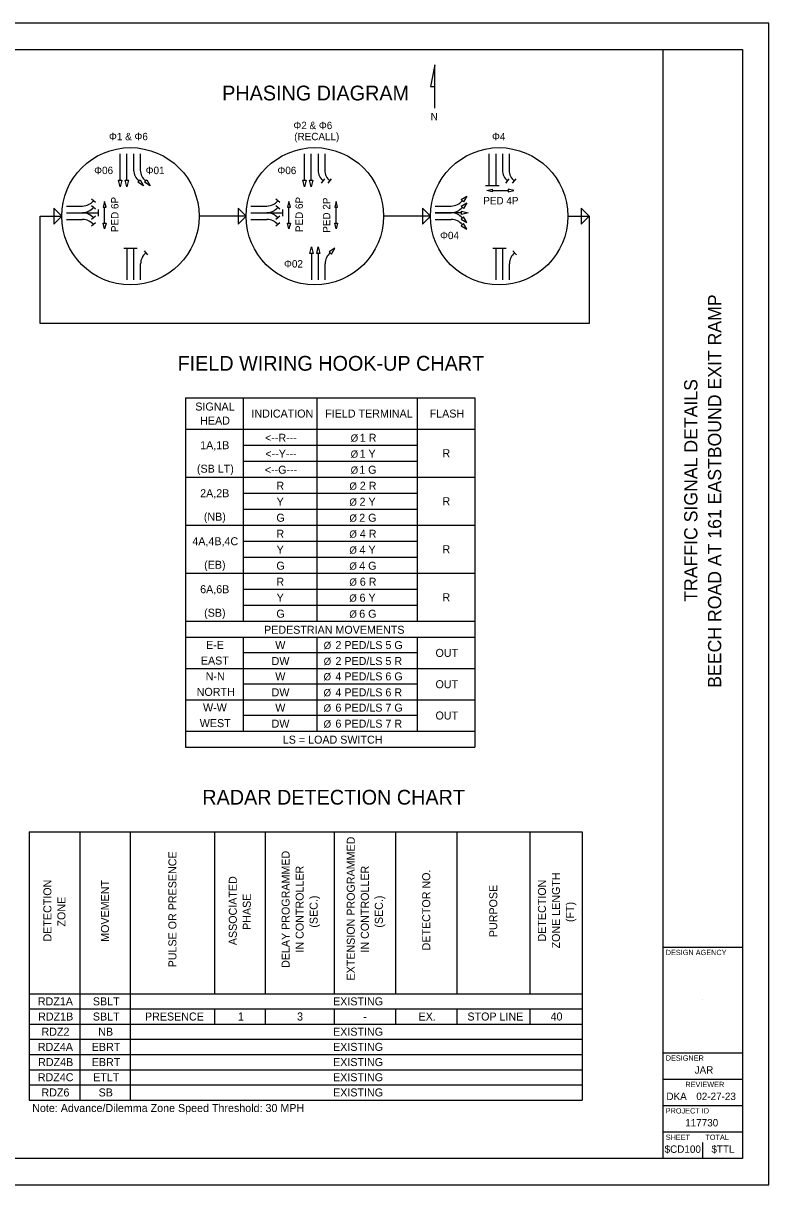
# Model space of a CAD drawing. Extents: x 0 to 34, y 0 to 22.
# Drawn here: x 19.89 to 34, y 0 to 22 of the extents above; entities that cross this region are included whole.
import ezdxf

# ---------------------------------------------------------------- set-up
doc = ezdxf.new("R2010")
doc.units = 0
for name, color, linetype in [('SG_P_Text', 7, 'Continuous'), ('SH_Border', 7, 'Continuous'), ('SH_Cut_Line', 7, 'Continuous'), ('SH_Data', 7, 'Continuous'), ('SH_Text', 7, 'Continuous')]:
    doc.layers.add(name, color=color, linetype=linetype)

msp = doc.modelspace()

# ---------------------------------------------------------------- linework, layer by layer
at = {"layer": 'SG_P_Text'}
for p, q in [((21.726, 19.026), (21.726, 19.524)), ((21.853, 19.026), (21.853, 19.524)), ((21.98, 19.524), (21.98, 19.218)), ((22.106, 19.524), (22.106, 19.218)), ((25.216, 19.026), (25.216, 19.524)), ((25.342, 19.026), (25.342, 19.524)), ((25.469, 19.524), (25.469, 19.218)), ((25.596, 19.524), (25.596, 19.218)), ((28.705, 19.524), (28.705, 18.923)), ((28.832, 19.524), (28.832, 18.923)), ((28.959, 19.524), (28.959, 19.218)), ((29.086, 19.524), (29.086, 19.218)), ((25.536, 18.972), (25.6, 19.051)), ((25.663, 18.972), (25.727, 19.051)), ((28.769, 18.923), (28.642, 18.923)), ((28.896, 18.923), (28.769, 18.923)), ((29.026, 18.972), (29.09, 19.051)), ((29.153, 18.972), (29.217, 19.051)), ((28.766, 18.832), (29.071, 18.832)), ((20.707, 18.538), (21.013, 18.538)), ((21.259, 18.605), (21.18, 18.669)), ((21.259, 18.478), (21.18, 18.543)), ((21.431, 18.213), (21.431, 18.518)), ((24.197, 18.538), (24.503, 18.538)), ((24.749, 18.605), (24.669, 18.669)), ((24.749, 18.478), (24.669, 18.543)), ((24.92, 18.213), (24.92, 18.518)), ((25.815, 18.213), (25.815, 18.518)), ((27.687, 18.538), (27.992, 18.538)), ((20.707, 18.412), (21.308, 18.412)), ((20.707, 18.412), (21.013, 18.412)), ((20.707, 18.412), (21.013, 18.412)), ((20.707, 18.285), (21.013, 18.285)), ((21.259, 18.345), (21.18, 18.281)), ((21.308, 18.475), (21.308, 18.348)), ((24.108, 18.344), (23.218, 18.344)), ((24.197, 18.412), (24.798, 18.412)), ((24.197, 18.412), (24.503, 18.412)), ((24.197, 18.412), (24.503, 18.412)), ((24.197, 18.285), (24.503, 18.285)), ((24.749, 18.345), (24.669, 18.281)), ((24.798, 18.475), (24.798, 18.348)), ((27.598, 18.344), (26.707, 18.344)), ((27.687, 18.412), (27.992, 18.412)), ((28.185, 18.412), (27.687, 18.412)), ((27.687, 18.412), (27.992, 18.412)), ((27.687, 18.285), (27.992, 18.285)), ((21.259, 18.218), (21.18, 18.154)), ((24.749, 18.218), (24.669, 18.154)), ((21.795, 17.74), (21.922, 17.74)), ((21.859, 17.139), (21.859, 17.74)), ((21.922, 17.74), (22.049, 17.74)), ((21.985, 17.139), (21.985, 17.74)), ((22.179, 17.691), (22.243, 17.611)), ((25.348, 17.637), (25.348, 17.139)), ((25.475, 17.637), (25.475, 17.139)), ((28.775, 17.74), (28.901, 17.74)), ((28.838, 17.139), (28.838, 17.74)), ((28.901, 17.74), (29.028, 17.74)), ((28.965, 17.139), (28.965, 17.74)), ((29.159, 17.691), (29.223, 17.611)), ((22.112, 17.139), (22.112, 17.445)), ((25.602, 17.139), (25.602, 17.445)), ((29.092, 17.139), (29.092, 17.445))]:
    msp.add_line(p, q, dxfattribs=at)
for points in [[(21.757, 19.026), (21.726, 18.901), (21.695, 19.026)], [(21.884, 19.026), (21.853, 18.901), (21.821, 19.026)], [(22.101, 19.034), (22.167, 18.923), (22.056, 18.989)], [(22.227, 19.034), (22.294, 18.923), (22.183, 18.989)], [(25.247, 19.026), (25.216, 18.901), (25.184, 19.026)], [(25.374, 19.026), (25.342, 18.901), (25.311, 19.026)], [(28.177, 18.659), (28.287, 18.726), (28.221, 18.615)], [(28.766, 18.806), (28.662, 18.832), (28.766, 18.858)], [(29.071, 18.806), (29.175, 18.832), (29.071, 18.858)], [(20.618, 18.344), (20.467, 18.496), (20.467, 18.193)], [(21.457, 18.518), (21.431, 18.622), (21.405, 18.518)], [(24.108, 18.344), (23.957, 18.496), (23.956, 18.193)], [(24.946, 18.518), (24.92, 18.622), (24.894, 18.518)], [(25.841, 18.518), (25.815, 18.622), (25.789, 18.518)], [(27.598, 18.344), (27.446, 18.496), (27.446, 18.193)], [(28.177, 18.533), (28.287, 18.599), (28.221, 18.488)], [(30.603, 18.344), (30.452, 18.496), (30.452, 18.193)], [(28.177, 18.29), (28.287, 18.224), (28.221, 18.335)], [(28.185, 18.443), (28.31, 18.412), (28.185, 18.38)], [(21.457, 18.213), (21.431, 18.108), (21.405, 18.213)], [(24.946, 18.213), (24.92, 18.108), (24.894, 18.213)], [(25.841, 18.213), (25.815, 18.108), (25.789, 18.213)], [(28.177, 18.164), (28.287, 18.098), (28.221, 18.208)], [(25.317, 17.637), (25.348, 17.762), (25.38, 17.637)], [(25.444, 17.637), (25.475, 17.762), (25.506, 17.637)], [(25.723, 17.629), (25.789, 17.74), (25.679, 17.673)]]:
    msp.add_lwpolyline(points, close=True, dxfattribs=at)
msp.add_lwpolyline([(30.197, 18.344), (30.603, 18.344), (30.603, 16.314), (20.618, 16.313), (20.212, 16.313), (20.212, 18.344), (20.618, 18.344)], dxfattribs=at)
for centre in [(21.918, 18.344), (25.408, 18.344), (28.897, 18.344)]:
    msp.add_circle(centre, 1.3, dxfattribs=at)
for centre, start, end in [((22.245, 19.218), 180, 231.2007), ((22.371, 19.218), 180, 231.2007), ((25.734, 19.218), 180, 231.2007), ((25.861, 19.218), 180, 231.2007), ((29.224, 19.218), 180, 231.2007), ((29.351, 19.218), 180, 231.2007), ((21.013, 18.803), 270, 321.2007), ((21.013, 18.677), 270, 321.2007), ((24.503, 18.803), 270, 321.2007), ((24.503, 18.677), 270, 321.2007), ((27.992, 18.803), 270, 321.2007), ((27.992, 18.677), 270, 321.2007), ((21.013, 18.147), 38.7993, 90), ((21.013, 18.02), 38.7993, 90), ((24.503, 18.147), 38.7993, 90), ((24.503, 18.02), 38.7993, 90), ((27.992, 18.147), 38.7993, 90), ((27.992, 18.02), 38.7993, 90), ((22.377, 17.445), 128.7993, 180), ((25.867, 17.445), 128.8122, 180.0129), ((29.357, 17.445), 128.7993, 180)]:
    msp.add_arc(centre, 0.265, start, end, dxfattribs=at)
at = {"layer": 'SH_Border'}
for p, q in [((32, 0.5), (32, 21.5)), ((32, 4.5), (33.5, 4.5)), ((32, 2.5), (33.5, 2.5)), ((32, 2), (33.5, 2)), ((32, 1.5), (33.5, 1.5)), ((32, 1), (33.5, 1))]:
    msp.add_line(p, q, dxfattribs=at)
msp.add_lwpolyline([(1.5, 21.5), (33.5, 21.5), (33.5, 0.5), (1.5, 0.5)], close=True, dxfattribs=at)
at = {"layer": 'SH_Cut_Line'}
msp.add_lwpolyline([(0, 0), (34, 0), (34, 22), (0, 22)], close=True, dxfattribs=at)
at = {"layer": 'SH_Data'}
for p, q in [((32.75, 3.5), (32.75, 3.5)), ((32.375, 0.675), (32.375, 0.675)), ((32.75, 0.5), (32.75, 0.8))]:
    msp.add_line(p, q, dxfattribs=at)
at = {"layer": 'SH_Text'}
for p, q in [((27.677, 20.389), (27.677, 21.209)), ((22.958, 14.903), (28.439, 14.903)), ((22.958, 14.903), (22.958, 14.007)), ((24.051, 14.903), (24.051, 14.007)), ((25.448, 14.903), (25.448, 14.007)), ((27.345, 14.903), (27.345, 14.007)), ((28.439, 14.903), (28.439, 14.007)), ((22.958, 14.31), (28.439, 14.31)), ((22.958, 14.007), (22.958, 13.401)), ((24.051, 14.007), (27.345, 14.007)), ((24.051, 14.007), (24.051, 13.401)), ((25.448, 14.007), (25.448, 13.401)), ((27.345, 14.007), (27.345, 13.401)), ((28.439, 14.007), (28.439, 13.401)), ((24.051, 13.704), (27.345, 13.704)), ((22.958, 13.401), (28.439, 13.401)), ((22.958, 13.401), (22.958, 11.886)), ((24.051, 13.401), (24.051, 11.886)), ((25.448, 13.401), (25.448, 11.886)), ((27.345, 13.401), (27.345, 11.886)), ((28.439, 13.401), (28.439, 11.886)), ((24.051, 13.098), (27.345, 13.098)), ((24.051, 12.795), (27.345, 12.795)), ((22.958, 12.492), (28.439, 12.492)), ((24.051, 12.189), (27.345, 12.189)), ((22.958, 11.886), (22.958, 11.583)), ((24.051, 11.886), (27.345, 11.886)), ((24.051, 11.886), (24.051, 11.583)), ((25.448, 11.886), (25.448, 11.583)), ((27.345, 11.886), (27.345, 11.583)), ((28.439, 11.886), (28.439, 11.583)), ((22.958, 11.583), (28.439, 11.583)), ((22.958, 11.583), (22.958, 11.28)), ((24.051, 11.583), (24.051, 11.28)), ((25.448, 11.583), (25.448, 11.28)), ((27.345, 11.583), (27.345, 11.28)), ((28.439, 11.583), (28.439, 11.28)), ((22.958, 11.28), (22.958, 10.674)), ((24.051, 11.28), (27.345, 11.28)), ((24.051, 11.28), (24.051, 10.674)), ((25.448, 11.28), (25.448, 10.674)), ((27.345, 11.28), (27.345, 10.674)), ((28.439, 11.28), (28.439, 10.674)), ((24.051, 10.977), (27.345, 10.977)), ((22.958, 10.674), (28.439, 10.674)), ((22.958, 10.674), (22.958, 9.488)), ((28.439, 10.674), (28.439, 9.488)), ((22.958, 10.371), (28.439, 10.371)), ((24.051, 10.371), (24.051, 9.488)), ((25.448, 10.371), (25.448, 9.488)), ((27.345, 10.371), (27.345, 9.488)), ((24.051, 10.081), (27.345, 10.081)), ((22.958, 9.778), (28.439, 9.778)), ((22.958, 9.488), (22.958, 9.185)), ((24.051, 9.488), (27.345, 9.488)), ((24.051, 9.488), (24.051, 9.185)), ((25.448, 9.488), (25.448, 9.185)), ((27.345, 9.488), (27.345, 9.185)), ((28.439, 9.488), (28.439, 9.185)), ((22.958, 9.185), (28.439, 9.185)), ((22.958, 9.185), (22.958, 8.895)), ((24.051, 9.185), (24.051, 8.895)), ((25.448, 9.185), (25.448, 8.895)), ((27.345, 9.185), (27.345, 8.895)), ((28.439, 9.185), (28.439, 8.895)), ((22.958, 8.895), (22.958, 8.592)), ((24.051, 8.895), (27.345, 8.895)), ((24.051, 8.895), (24.051, 8.592)), ((25.448, 8.895), (25.448, 8.592)), ((27.345, 8.895), (27.345, 8.592)), ((28.439, 8.895), (28.439, 8.592)), ((22.958, 8.592), (28.439, 8.592)), ((22.958, 8.592), (22.958, 8.289)), ((28.439, 8.592), (28.439, 8.289)), ((22.958, 8.289), (28.439, 8.289)), ((20, 6.684), (25.774, 6.684)), ((20, 6.684), (20, 2.755)), ((20.959, 6.684), (20.959, 2.755)), ((21.917, 6.684), (21.917, 2.755)), ((23.51, 6.684), (23.51, 3.618)), ((24.468, 6.684), (24.468, 3.618)), ((25.774, 6.684), (28.098, 6.684)), ((25.774, 6.684), (25.774, 3.618)), ((26.936, 6.684), (26.936, 3.618)), ((28.098, 6.684), (30.47, 6.684)), ((28.098, 6.684), (28.098, 3.618)), ((29.475, 6.684), (29.475, 3.618)), ((30.47, 6.684), (30.47, 2.755)), ((20, 3.618), (25.774, 3.618)), ((25.774, 3.618), (28.098, 3.618)), ((28.098, 3.618), (30.47, 3.618)), ((20, 3.33), (25.774, 3.33)), ((23.51, 3.33), (23.51, 3.043)), ((24.468, 3.33), (24.468, 3.043)), ((25.774, 3.33), (28.098, 3.33)), ((25.774, 3.33), (25.774, 3.043)), ((26.936, 3.33), (26.936, 3.043)), ((28.098, 3.33), (30.47, 3.33)), ((28.098, 3.33), (28.098, 3.043)), ((29.475, 3.33), (29.475, 3.043)), ((20, 3.043), (25.774, 3.043)), ((25.774, 3.043), (28.098, 3.043)), ((28.098, 3.043), (30.47, 3.043)), ((20, 2.755), (25.774, 2.755)), ((20, 2.755), (20, 1.893)), ((20.959, 2.755), (20.959, 1.893)), ((21.917, 2.755), (21.917, 1.893)), ((25.774, 2.755), (28.098, 2.755)), ((28.098, 2.755), (30.47, 2.755)), ((30.47, 2.755), (30.47, 1.893)), ((20, 2.468), (25.774, 2.468)), ((25.774, 2.468), (28.098, 2.468)), ((28.098, 2.468), (30.47, 2.468)), ((20, 2.18), (25.774, 2.18)), ((25.774, 2.18), (28.098, 2.18)), ((28.098, 2.18), (30.47, 2.18)), ((20, 1.893), (25.774, 1.893)), ((20, 1.893), (20, 1.605)), ((20.959, 1.893), (20.959, 1.605)), ((21.917, 1.893), (21.917, 1.605)), ((25.774, 1.893), (28.098, 1.893)), ((28.098, 1.893), (30.47, 1.893)), ((30.47, 1.893), (30.47, 1.605)), ((20, 1.605), (25.774, 1.605)), ((25.774, 1.605), (28.098, 1.605)), ((28.098, 1.605), (30.47, 1.605))]:
    msp.add_line(p, q, dxfattribs=at)
msp.add_lwpolyline([(27.677, 21.209), (27.595, 20.799), (27.677, 20.799)], close=True, dxfattribs=at)

# ---------------------------------------------------------------- texts
at = {"layer": 'SG_P_Text'}
for s, height, p in [('PHASING DIAGRAM', 0.28, (23.655, 20.538)), ('Φ2 & Φ6', 0.14, (25.003, 19.994)), ('Φ1 & Φ6', 0.14, (21.513, 19.784)), ('(RECALL)', 0.14, (25.019, 19.784)), ('Φ4', 0.14, (28.762, 19.784)), ('Φ06', 0.14, (21.233, 19.142)), ('Φ01', 0.14, (22.207, 19.142)), ('Φ06', 0.14, (24.701, 19.142)), ('PED 4P', 0.14, (28.597, 18.569)), ('Φ04', 0.14, (27.779, 17.91)), ('Φ02', 0.14, (24.826, 17.373)), ('FIELD WIRING HOOK-UP CHART', 0.28, (22.811, 15.419)), ('RADAR DETECTION CHART', 0.28, (23.279, 7.2))]:
    msp.add_text(s, height=height, dxfattribs=at).set_placement(p)
for s, p in [('PED 6P', (21.693, 18.044)), ('PED 6P', (25.183, 18.044)), ('PED 2P', (25.701, 18.032))]:
    msp.add_text(s, height=0.14, rotation=90, dxfattribs=at).set_placement(p)
at = {"layer": 'SH_Data'}
for s, p in [('BEECH ROAD AT 161 EASTBOUND EXIT RAMP', (33.1, 9.414)), ('TRAFFIC SIGNAL DETAILS', (32.65, 11.043))]:
    msp.add_text(s, height=0.25, rotation=90, dxfattribs=at).set_placement(p)
for s, height, p in [('DESIGN AGENCY', 0.1, (32.05, 4.35)), ('DESIGNER', 0.1, (32.05, 2.35)), ('JAR', 0.14, (32.597, 2.105)), ('REVIEWER', 0.1, (32.422, 1.85)), ('DKA', 0.14, (32.063, 1.605)), ('02-27-23', 0.14, (32.629, 1.605)), ('PROJECT ID', 0.1, (32.05, 1.35)), ('117730', 0.14, (32.419, 1.105)), ('SHEET', 0.1, (32.05, 0.85)), ('TOTAL', 0.1, (32.8, 0.85)), ('$CD100', 0.14, (32.029, 0.605)), ('$TTL', 0.14, (32.915, 0.605))]:
    msp.add_text(s, height=height, dxfattribs=at).set_placement(p)
at = {"layer": 'SH_Text'}
for s, height, p in [('N', 0.14, (27.601, 20.161)), ('SIGNAL ', 0.1515, (23.147, 14.664)), ('HEAD', 0.1515, (23.239, 14.398)), ('INDICATION', 0.1515, (24.209, 14.531)), ('FIELD TERMINAL', 0.15153, (25.606, 14.531)), ('FLASH', 0.1515, (27.582, 14.531)), ('1A,1B', 0.1515, (23.239, 13.932)), ('<--R---', 0.1515, (24.467, 14.073)), ('Ø', 0.137, (26.087, 14.075)), ('1 R', 0.1515, (26.26, 14.073)), ('<--Y---', 0.1515, (24.473, 13.77)), ('Ø', 0.137, (26.087, 13.771)), ('1 Y', 0.1515, (26.255, 13.77)), ('R', 0.152, (27.824, 13.78)), ('(SB LT)', 0.1515, (23.178, 13.487)), ('<--G---', 0.1515, (24.462, 13.467)), ('Ø', 0.137, (26.087, 13.468)), ('1 G', 0.1515, (26.249, 13.467)), ('R', 0.152, (24.681, 13.164)), ('Ø', 0.137, (26.064, 13.165)), ('2 R', 0.1515, (26.26, 13.164)), ('2A,2B', 0.1515, (23.239, 13.022)), ('Y', 0.152, (24.686, 12.861)), ('Ø', 0.137, (26.063, 12.862)), ('2 Y', 0.1515, (26.255, 12.861)), ('R', 0.152, (27.824, 12.871)), ('(NB)', 0.1515, (23.308, 12.578)), ('G', 0.152, (24.681, 12.558)), ('Ø', 0.137, (26.064, 12.559)), ('2 G', 0.1515, (26.249, 12.558)), ('R', 0.152, (24.681, 12.255)), ('Ø', 0.137, (26.062, 12.256)), ('4 R', 0.1515, (26.26, 12.255)), ('4A,4B,4C', 0.1515, (23.091, 12.113)), ('Y', 0.152, (24.686, 11.952)), ('4 Y', 0.1515, (26.255, 11.952)), ('R', 0.152, (27.824, 11.962)), ('Ø', 0.137, (26.062, 11.953)), ('(EB)', 0.1515, (23.314, 11.668)), ('G', 0.152, (24.681, 11.649)), ('Ø', 0.137, (26.062, 11.65)), ('4 G', 0.1515, (26.249, 11.649)), ('R', 0.152, (24.681, 11.346)), ('Ø', 0.137, (26.062, 11.347)), ('6 R', 0.1515, (26.26, 11.346)), ('6A,6B', 0.1515, (23.239, 11.204)), ('Y', 0.152, (24.686, 11.043)), ('Ø', 0.137, (26.061, 11.044)), ('6 Y', 0.1515, (26.255, 11.043)), ('R', 0.152, (27.824, 11.052)), ('(SB)', 0.1515, (23.314, 10.759)), ('G', 0.152, (24.681, 10.74)), ('Ø', 0.137, (26.062, 10.741)), ('6 G', 0.1515, (26.249, 10.74)), ('PEDESTRIAN MOVEMENTS', 0.15153, (24.448, 10.436)), ('E-E', 0.1515, (23.35, 10.15)), ('W', 0.152, (24.66, 10.147)), ('Ø', 0.137, (25.576, 10.148)), ('2 PED/LS 5 G', 0.15153, (25.799, 10.147)), ('OUT', 0.1515, (27.693, 9.998)), ('EAST', 0.1515, (23.252, 9.853)), ('DW', 0.1515, (24.591, 9.844)), ('Ø', 0.137, (25.576, 9.845)), ('2 PED/LS 5 R', 0.15153, (25.799, 9.844)), ('N-N', 0.1515, (23.343, 9.557)), ('W', 0.152, (24.66, 9.554)), ('Ø', 0.137, (25.574, 9.555)), ('4 PED/LS 6 G', 0.15153, (25.799, 9.554)), ('OUT', 0.1515, (27.693, 9.405)), ('NORTH', 0.1515, (23.173, 9.26)), ('DW', 0.1515, (24.591, 9.251)), ('Ø', 0.137, (25.574, 9.252)), ('4 PED/LS 6 R', 0.15153, (25.799, 9.251)), ('W-W', 0.1515, (23.293, 8.964)), ('W', 0.152, (24.66, 8.961)), ('Ø', 0.137, (25.575, 8.962)), ('6 PED/LS 7 G', 0.15153, (25.799, 8.961)), ('WEST', 0.1515, (23.231, 8.668)), ('DW', 0.1515, (24.591, 8.658)), ('Ø', 0.137, (25.575, 8.659)), ('6 PED/LS 7 R', 0.15153, (25.799, 8.658)), ('OUT', 0.1515, (27.693, 8.812)), ('LS = LOAD SWITCH', 0.15153, (24.803, 8.355)), ('RDZ1A', 0.1515, (20.167, 3.398)), ('SBLT', 0.1515, (21.208, 3.398)), ('EXISTING', 0.1515, (25.754, 3.398)), ('RDZ1B', 0.1515, (20.172, 3.111)), ('SBLT', 0.1515, (21.208, 3.111)), ('PRESENCE', 0.1515, (22.194, 3.111)), ('1', 0.152, (23.954, 3.111)), ('3', 0.152, (25.072, 3.111)), ('-', 0.152, (26.326, 3.111)), ('EX.', 0.1515, (27.372, 3.111)), ('STOP LINE', 0.1515, (28.297, 3.111)), ('40', 0.1515, (29.871, 3.111)), ('RDZ2', 0.1515, (20.236, 2.823)), ('NB', 0.1515, (21.31, 2.823)), ('EXISTING', 0.1515, (25.754, 2.823)), ('RDZ4A', 0.1515, (20.167, 2.536)), ('EBRT', 0.1515, (21.187, 2.536)), ('EXISTING', 0.1515, (25.754, 2.536)), ('RDZ4B', 0.1515, (20.172, 2.248)), ('EBRT', 0.1515, (21.187, 2.248)), ('EXISTING', 0.1515, (25.754, 2.248)), ('RDZ4C', 0.1515, (20.166, 1.961)), ('ETLT', 0.1515, (21.214, 1.961)), ('EXISTING', 0.1515, (25.754, 1.961)), ('RDZ6', 0.1515, (20.235, 1.673)), ('SB', 0.1515, (21.316, 1.673)), ('EXISTING', 0.1515, (25.754, 1.673)), ('Note: Advance/Dilemma Zone Speed Threshold: 30 MPH', 0.15153, (20.06, 1.378))]:
    msp.add_text(s, height=height, dxfattribs=at).set_placement(p)
for s, height, p in [('EXTENSION PROGRAMMED', 0.15153, (26.165, 3.869)), ('PULSE OR PRESENCE', 0.15153, (22.789, 4.118)), ('DELAY PROGRAMMED', 0.15153, (24.932, 4.107)), (' IN CONTROLLER', 0.15153, (25.197, 4.342)), (' IN CONTROLLER', 0.15153, (26.431, 4.342)), ('DETECTOR NO.', 0.15153, (27.593, 4.439)), ('DETECTION', 0.1515, (20.423, 4.608)), ('MOVEMENT', 0.1515, (21.513, 4.602)), ('ASSOCIATED', 0.1515, (23.932, 4.538)), ('DETECTION', 0.1515, (29.783, 4.608)), ('ZONE LENGTH', 0.15153, (30.048, 4.476)), ('PHASE', 0.1515, (24.197, 4.827)), ('PURPOSE', 0.1515, (28.862, 4.69)), ('ZONE', 0.1515, (20.688, 4.891)), ('(SEC.)', 0.1515, (25.462, 4.87)), ('(SEC.)', 0.1515, (26.696, 4.87)), ('(FT)', 0.1515, (30.313, 4.976))]:
    msp.add_text(s, height=height, rotation=90, dxfattribs=at).set_placement(p)

doc.saveas('drawing.dxf')
